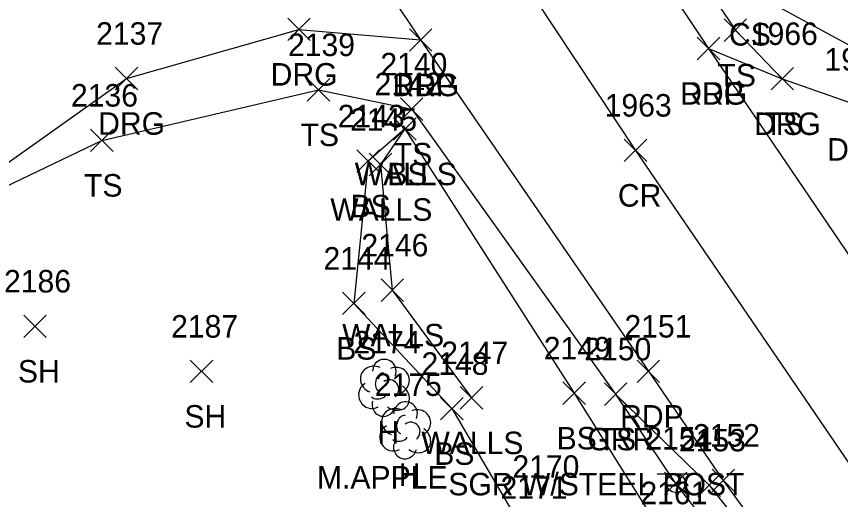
# Model space of a CAD drawing. Extents: x 1501299 to 1502485, y 381423 to 383765.
# Drawn here: x 1501524.4 to 1501597.6, y 383324.5 to 383367.4 of the extents above; entities that cross this region are included whole.
import ezdxf

# ---------------------------------------------------------------- set-up
doc = ezdxf.new("R2010")
doc.units = 0
for name, color, linetype in [('L_A', 7, 'Continuous'), ('L_C', 7, 'Continuous'), ('L_I', 7, 'Continuous'), ('L_TIC', 7, 'Continuous'), ('LELB', 7, 'Continuous'), ('LTD', 7, 'Continuous'), ('LWS', 7, 'Continuous'), ('P_A', 7, 'Continuous'), ('P_I', 7, 'Continuous'), ('P_TIC', 7, 'Continuous'), ('PET', 7, 'Continuous'), ('PRC', 7, 'Continuous'), ('R_A', 7, 'Continuous'), ('R_C', 7, 'Continuous'), ('R_I', 7, 'Continuous'), ('R_TIC', 7, 'Continuous'), ('RDG', 7, 'Continuous'), ('RGR', 7, 'Continuous'), ('S_I', 7, 'Continuous'), ('SSGN', 7, 'Continuous')]:
    doc.layers.add(name, color=color, linetype=linetype)

msp = doc.modelspace()

# ---------------------------------------------------------------- linework, layer by layer
at = {"layer": 'L_TIC'}
for points in [[(1501587.278, 383365.162), (1501589.278, 383367.162)], [(1501589.278, 383365.162), (1501587.278, 383367.162)], [(1501591.449, 383360.853), (1501593.449, 383362.853)], [(1501593.449, 383360.853), (1501591.449, 383362.853)], [(1501550.241, 383359.865), (1501552.241, 383361.865)], [(1501552.241, 383359.865), (1501550.241, 383361.865)], [(1501558.526, 383358.149), (1501560.526, 383360.149)], [(1501560.526, 383358.149), (1501558.526, 383360.149)], [(1501557.924, 383356.388), (1501559.924, 383358.388)], [(1501559.924, 383356.388), (1501557.924, 383358.388)], [(1501557.924, 383356.388), (1501559.924, 383358.388)], [(1501559.924, 383356.388), (1501557.924, 383358.388)], [(1501557.924, 383356.388), (1501559.924, 383358.388)], [(1501559.924, 383356.388), (1501557.924, 383358.388)], [(1501531.009, 383355.376), (1501533.009, 383357.376)], [(1501533.009, 383355.376), (1501531.009, 383357.376)], [(1501554.653, 383353.535), (1501556.653, 383355.535)], [(1501556.653, 383353.535), (1501554.653, 383355.535)], [(1501555.749, 383353.229), (1501557.749, 383355.229)], [(1501557.749, 383353.229), (1501555.749, 383355.229)], [(1501556.805, 383342.066), (1501558.805, 383344.066)], [(1501558.805, 383342.066), (1501556.805, 383344.066)], [(1501553.386, 383340.888), (1501555.386, 383342.888)], [(1501555.386, 383340.888), (1501553.386, 383342.888)], [(1501525.063, 383338.856), (1501527.063, 383340.856)], [(1501527.063, 383338.856), (1501525.063, 383340.856)], [(1501539.85, 383334.848), (1501541.85, 383336.848)], [(1501541.85, 383334.848), (1501539.85, 383336.848)], [(1501572.959, 383332.908), (1501574.959, 383334.908)], [(1501574.959, 383332.908), (1501572.959, 383334.908)], [(1501576.64, 383332.828), (1501578.64, 383334.828)], [(1501578.64, 383332.828), (1501576.64, 383334.828)], [(1501563.842, 383332.49), (1501565.842, 383334.49)], [(1501565.842, 383332.49), (1501563.842, 383334.49)], [(1501562.091, 383331.538), (1501564.091, 383333.538)], [(1501564.091, 383331.538), (1501562.091, 383333.538)], [(1501581.97, 383324.895), (1501583.97, 383326.895)], [(1501583.97, 383324.895), (1501581.97, 383326.895)]]:
    msp.add_lwpolyline(points, dxfattribs=at)
at = {"layer": 'LELB'}
for points in [[(1501358.62, 383732.982), (1501381.143, 383696.09), (1501398.686, 383667.715), (1501415.463, 383640.286), (1501435.304, 383603.989), (1501464.895, 383561.231), (1501485.321, 383525.1), (1501505.057, 383497.042), (1501522.935, 383468.146), (1501546.418, 383435.546), (1501564.602, 383407.152), (1501589.271, 383369.799), (1501600.381, 383363.765)], [(1501355.507, 383731.142), (1501378.372, 383693.856), (1501395.554, 383665.66), (1501411.452, 383638.214), (1501433.323, 383602.627), (1501461.336, 383558.643), (1501483.164, 383524.052), (1501502.066, 383494.506), (1501520.426, 383466.229), (1501542.016, 383433.96), (1501561.692, 383405.395), (1501588.278, 383366.162), (1501592.449, 383361.853)], [(1501514.863, 383348.169), (1501532.009, 383356.376), (1501551.241, 383360.865), (1501559.526, 383359.149), (1501577.64, 383333.828), (1501582.97, 383325.895), (1501599.37, 383304.818)], [(1501558.924, 383357.388), (1501555.653, 383354.535), (1501554.386, 383341.888), (1501563.091, 383332.538), (1501569.542, 383321.529), (1501576.131, 383315.049), (1501582.343, 383306.021), (1501584.514, 383303.868), (1501586.804, 383304.65)], [(1501558.924, 383357.388), (1501573.959, 383333.908), (1501582.018, 383321.04), (1501588.751, 383310.663), (1501590.251, 383306.118)]]:
    msp.add_lwpolyline(points, dxfattribs=at)
at = {"layer": 'LTD'}
for p, q in [((1501557.051, 383334.436), (1501557.051, 383334.436)), ((1501557.051, 383334.436), (1501557.051, 383334.436)), ((1501558.942, 383330.665), (1501558.942, 383330.665)), ((1501558.942, 383330.665), (1501558.942, 383330.665))]:
    msp.add_line(p, q, dxfattribs=at)
for centre in [(1501557.098, 383335.87), (1501558.989, 383332.099)]:
    msp.add_arc(centre, 1.047, 335.52715, 180.95627, dxfattribs=at)
for centre, major_axis, ratio, start_param, end_param in [((1501556.259, 383335.102), (1.21, -0.512), 0.895232, 1.570796, 4.712389), ((1501558.093, 383335.019), (-1.141, -0.483), 0.949671, 1.570796, 4.712389), ((1501556.843, 383334.894), (-0.208, -0.792), 0.645439, 3.141593, 6.283185), ((1501555.968, 383333.727), (0.584, -1.042), 0.959034, 3.141593, 6.283185), ((1501557.551, 383334.269), (-0.5, 0.667), 0.989748, 3.141593, 6.283185), ((1501558.051, 383333.602), (-1.09, 0.792), 0.841452, 1.570796, 4.712389), ((1501556.593, 383333.685), (-0.625, -0.083), 0.423636, 0, 3.141593), ((1501557.051, 383332.936), (0.265, 1.061), 0.942809, 1.570796, 4.712389), ((1501558.15, 383331.332), (1.21, -0.512), 0.895232, 1.570796, 4.712389), ((1501559.984, 383331.249), (-1.141, -0.483), 0.949671, 1.570796, 4.712389), ((1501558.734, 383331.123), (-0.208, -0.792), 0.645439, 3.141593, 6.283185), ((1501559.442, 383330.499), (-0.5, 0.667), 0.989748, 3.141593, 6.283185), ((1501557.859, 383329.957), (0.584, -1.042), 0.959034, 3.141593, 6.283185), ((1501559.942, 383329.832), (-1.09, 0.792), 0.841452, 1.570796, 4.712389), ((1501558.484, 383329.915), (-0.625, -0.083), 0.423636, 0, 3.141593), ((1501558.943, 383329.165), (0.265, 1.061), 0.942809, 1.570796, 4.712389)]:
    msp.add_ellipse(centre, major_axis=major_axis, ratio=ratio, start_param=start_param, end_param=end_param, dxfattribs=at)
at = {"layer": 'LWS'}
msp.add_lwpolyline([(1501558.924, 383357.388), (1501556.749, 383354.229), (1501557.805, 383343.066), (1501564.842, 383333.49)], dxfattribs=at)
at = {"layer": 'P_TIC'}
for points in [[(1501559.323, 383364.298), (1501561.323, 383366.298)], [(1501561.323, 383364.298), (1501559.323, 383366.298)], [(1501584.888, 383363.546), (1501586.888, 383365.546)], [(1501586.888, 383363.546), (1501584.888, 383365.546)], [(1501578.411, 383354.488), (1501580.411, 383356.488)], [(1501580.411, 383354.488), (1501578.411, 383356.488)], [(1501579.554, 383334.852), (1501581.554, 383336.852)], [(1501581.554, 383334.852), (1501579.554, 383336.852)], [(1501586.206, 383325.159), (1501588.206, 383327.159)], [(1501588.206, 383325.159), (1501586.206, 383327.159)]]:
    msp.add_lwpolyline(points, dxfattribs=at)
at = {"layer": 'PET'}
for points in [[(1501352.609, 383730.103), (1501376.04, 383692.663), (1501392.886, 383664.453), (1501409.551, 383637.048), (1501431.218, 383601.012), (1501459.286, 383556.771), (1501480.727, 383522.39), (1501500.041, 383493.106), (1501518.668, 383465.088), (1501539.809, 383433.288), (1501559.66, 383403.845), (1501585.888, 383364.546), (1501607.043, 383333.417), (1501616.485, 383318.818), (1501608.79, 383312.411), (1501601.645, 383306.284)], [(1501334.826, 383720.255), (1501358.007, 383682.468), (1501375.272, 383653.985), (1501391.807, 383626.284), (1501413.667, 383590.156), (1501441.928, 383545.301), (1501463.314, 383511.64), (1501483.045, 383481.713), (1501501.394, 383453.556), (1501521.788, 383422.955), (1501532.703, 383406.598), (1501560.323, 383365.298), (1501580.554, 383335.852), (1501587.206, 383326.159), (1501601.645, 383306.284)]]:
    msp.add_lwpolyline(points, dxfattribs=at)
at = {"layer": 'PRC'}
msp.add_lwpolyline([(1501342.033, 383724.182), (1501367.312, 383687.902), (1501383.586, 383659.523), (1501401.023, 383631.482), (1501422.762, 383595.527), (1501451.018, 383550.575), (1501471.941, 383517.221), (1501491.454, 383487.691), (1501510.587, 383459.001), (1501530.118, 383428.738), (1501550.992, 383398.393), (1501579.411, 383355.488), (1501608.79, 383312.411)], dxfattribs=at)
at = {"layer": 'R_TIC'}
for points in [[(1501548.512, 383365.241), (1501550.512, 383367.241)], [(1501550.512, 383365.241), (1501548.512, 383367.241)], [(1501559.323, 383364.298), (1501561.323, 383366.298)], [(1501561.323, 383364.298), (1501559.323, 383366.298)], [(1501584.888, 383363.546), (1501586.888, 383365.546)], [(1501586.888, 383363.546), (1501584.888, 383365.546)], [(1501533.189, 383360.876), (1501535.189, 383362.876)], [(1501535.189, 383360.876), (1501533.189, 383362.876)], [(1501591.449, 383360.853), (1501593.449, 383362.853)], [(1501593.449, 383360.853), (1501591.449, 383362.853)], [(1501576.64, 383332.828), (1501578.64, 383334.828)], [(1501578.64, 383332.828), (1501576.64, 383334.828)], [(1501584.957, 383324.738), (1501586.957, 383326.738)], [(1501586.957, 383324.738), (1501584.957, 383326.738)]]:
    msp.add_lwpolyline(points, dxfattribs=at)
at = {"layer": 'RDG'}
for points in [[(1501585.888, 383364.546), (1501592.449, 383361.853), (1501598.939, 383359.572), (1501609.156, 383359.828), (1501620.557, 383365.386), (1501633.637, 383372.08), (1501645.617, 383382.098), (1501657.095, 383388.246), (1501660.515, 383391.446), (1501681.22, 383404.169), (1501705.776, 383415.265), (1501726.712, 383424.327)], [(1501445.866, 383299.066), (1501467.724, 383312.153), (1501488.926, 383329.334), (1501514.863, 383348.169), (1501534.189, 383361.876), (1501549.512, 383366.241), (1501560.323, 383365.298)]]:
    msp.add_lwpolyline(points, dxfattribs=at)
at = {"layer": 'RGR'}
msp.add_lwpolyline([(1501577.64, 383333.828), (1501585.957, 383325.738), (1501601.432, 383306.001)], dxfattribs=at)
at = {"layer": 'SSGN'}
for p, q in [((1501581.343, 383326.749), (1501584.676, 383326.749)), ((1501582.99, 383325.915), (1501582.99, 383325.915))]:
    msp.add_line(p, q, dxfattribs=at)
msp.add_circle((1501582.99, 383325.915), 0.833, dxfattribs=at)

# ---------------------------------------------------------------- texts
at = {"layer": 'L_A'}
for s, p in [('CS', (1501587.712, 383364.799)), ('TS', (1501586.688, 383361.162)), ('TS', (1501590.859, 383356.853)), ('TS', (1501549.65, 383355.865)), ('TS', (1501557.935, 383354.149)), ('WALLS', (1501554.467, 383352.388)), ('BS', (1501557.365, 383352.388)), ('BS', (1501557.365, 383352.388)), ('TS', (1501530.419, 383351.376)), ('WALLS', (1501552.293, 383349.229)), ('BS', (1501554.094, 383349.535)), ('WALLS', (1501553.348, 383338.066)), ('BS', (1501552.827, 383336.888)), ('SH', (1501524.551, 383334.856)), ('SH', (1501539.338, 383330.848)), ('H', (1501556.484, 383329.436)), ('WALLS', (1501560.386, 383328.49)), ('BS', (1501572.399, 383328.908)), ('TS', (1501576.05, 383328.828)), ('BS', (1501561.532, 383327.538)), ('H', (1501558.375, 383325.665))]:
    msp.add_text(s, height=2, dxfattribs=at).set_placement(p)
at = {"layer": 'L_C'}
msp.add_text('M.APPLE', height=2, dxfattribs=at).set_placement((1501551.114, 383325.436))
at = {"layer": 'L_I'}
for s, p in [('1966', (1501589.654, 383364.853)), ('2139', (1501548.54, 383363.865)), ('2140', (1501556.746, 383362.149)), ('2142', (1501556.231, 383360.388)), ('2142', (1501556.231, 383360.388)), ('2142', (1501556.231, 383360.388)), ('2136', (1501529.262, 383359.376)), ('2143', (1501552.96, 383357.535)), ('2145', (1501554.056, 383357.229)), ('2146', (1501555.057, 383346.066)), ('2144', (1501551.693, 383344.888)), ('2186', (1501523.315, 383342.856)), ('2187', (1501538.158, 383338.848)), ('2174', (1501554.359, 383337.436)), ('2147', (1501562.149, 383336.49)), ('2149', (1501571.258, 383336.908)), ('2150', (1501574.861, 383336.828)), ('2148', (1501560.398, 383335.538)), ('2175', (1501556.25, 383333.665)), ('2154', (1501580.277, 383328.895)), ('2170', (1501568.474, 383326.387)), ('2171', (1501567.417, 383324.529)), ('2161', (1501579.845, 383324.04))]:
    msp.add_text(s, height=2, dxfattribs=at).set_placement(p)
at = {"layer": 'P_A'}
for s, p in [('RDP', (1501557.811, 383360.298)), ('RDP', (1501583.376, 383359.546)), ('CR', (1501577.844, 383350.488)), ('RDP', (1501578.042, 383330.852))]:
    msp.add_text(s, height=2, dxfattribs=at).set_placement(p)
at = {"layer": 'P_I'}
for s, p in [('1963', (1501576.671, 383358.488)), ('2151', (1501578.428, 383338.852)), ('2152', (1501584.513, 383329.159))]:
    msp.add_text(s, height=2, dxfattribs=at).set_placement(p)
at = {"layer": 'R_A'}
for s, p in [('DRG', (1501547, 383361.241)), ('DRG', (1501557.811, 383360.298)), ('DRG', (1501583.376, 383359.546)), ('DRG', (1501531.677, 383356.876)), ('DRG', (1501589.938, 383356.853)), ('DRG', (1501596.427, 383354.572)), ('GRR', (1501575.128, 383328.828))]:
    msp.add_text(s, height=2, dxfattribs=at).set_placement(p)
at = {"layer": 'R_C'}
msp.add_text('SGR W/STEEL POST', height=2, dxfattribs=at).set_placement((1501562.782, 383324.828))
at = {"layer": 'R_I'}
for s, p in [('2137', (1501531.496, 383364.876)), ('1966', (1501589.654, 383364.853)), ('1967', (1501596.199, 383362.572)), ('2150', (1501574.861, 383336.828)), ('2153', (1501583.265, 383328.738))]:
    msp.add_text(s, height=2, dxfattribs=at).set_placement(p)
at = {"layer": 'S_I'}
msp.add_text('2154', height=2, dxfattribs=at).set_placement((1501580.277, 383328.895))

doc.saveas('drawing.dxf')
